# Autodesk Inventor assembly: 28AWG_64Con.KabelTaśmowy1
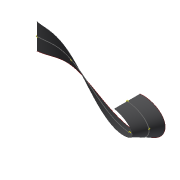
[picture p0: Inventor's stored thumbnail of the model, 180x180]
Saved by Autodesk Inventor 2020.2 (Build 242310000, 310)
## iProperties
Manager: www.cadconsulting.pl
Company: Fabian Stasiak CAD Consulting
Part Number: 28AWG_64Con.KabelTaśmowy1
Material: Ogólne
Description: 28AWG_64Con
Created: 2014-09
Part Number: T_300_01.Wiązka przewodów1
Document SubType Name: Assembly
Designer: F.Stasiak
Catalog Web Link: www.expertbooks.pl
ParentFileIdentifier: 5|1|0|0|50|1|0|0|80|0|65|0|84|0|72|0|83|0|59|0|67|0|58|0|92|0|90|0|98|0|105|0|243|0|114|0|32|0|7|1|119|0|105|0|99|0|122|0|101|0|68|1|32|0|65|0|73|0|32|0|50|0|48
HarnessSettings: <HarnessSettings><Defaults><Segments><Diameter value="0.200 in" fromwires="True"/><Offset value="0.100 in"/><ColorStyle value="Niebieska - farba ścienna - lśnią
Author: F.Stasiak
Subject: Zbiór ćwiczeń. Autodesk Inventor 2020. Kurs Professional
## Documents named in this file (2)
- C:\2020_Kurs_Professional\R2 Wiązki\T_300_01\AIP\przewody i wiązki przewodów\T_300_01.Wiązka przewodów1.iam
- C:\2020_Kurs_Professional\R2 Wiązki\T_300_01\AIP\przewody i wiązki przewodów\T_300_01.Wiązka przewodów1.ipt
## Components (2 placed, 2 different names)
1. Wiązka przewodów1
2. HA_VC_128:1
